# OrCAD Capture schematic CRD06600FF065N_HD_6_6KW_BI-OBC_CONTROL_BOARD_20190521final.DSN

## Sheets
1 PAGE5: size A3; title: 6.6kW HD Bi-directional OBC Control Board; rev: 3; note: P/N: CRD06600FF065N
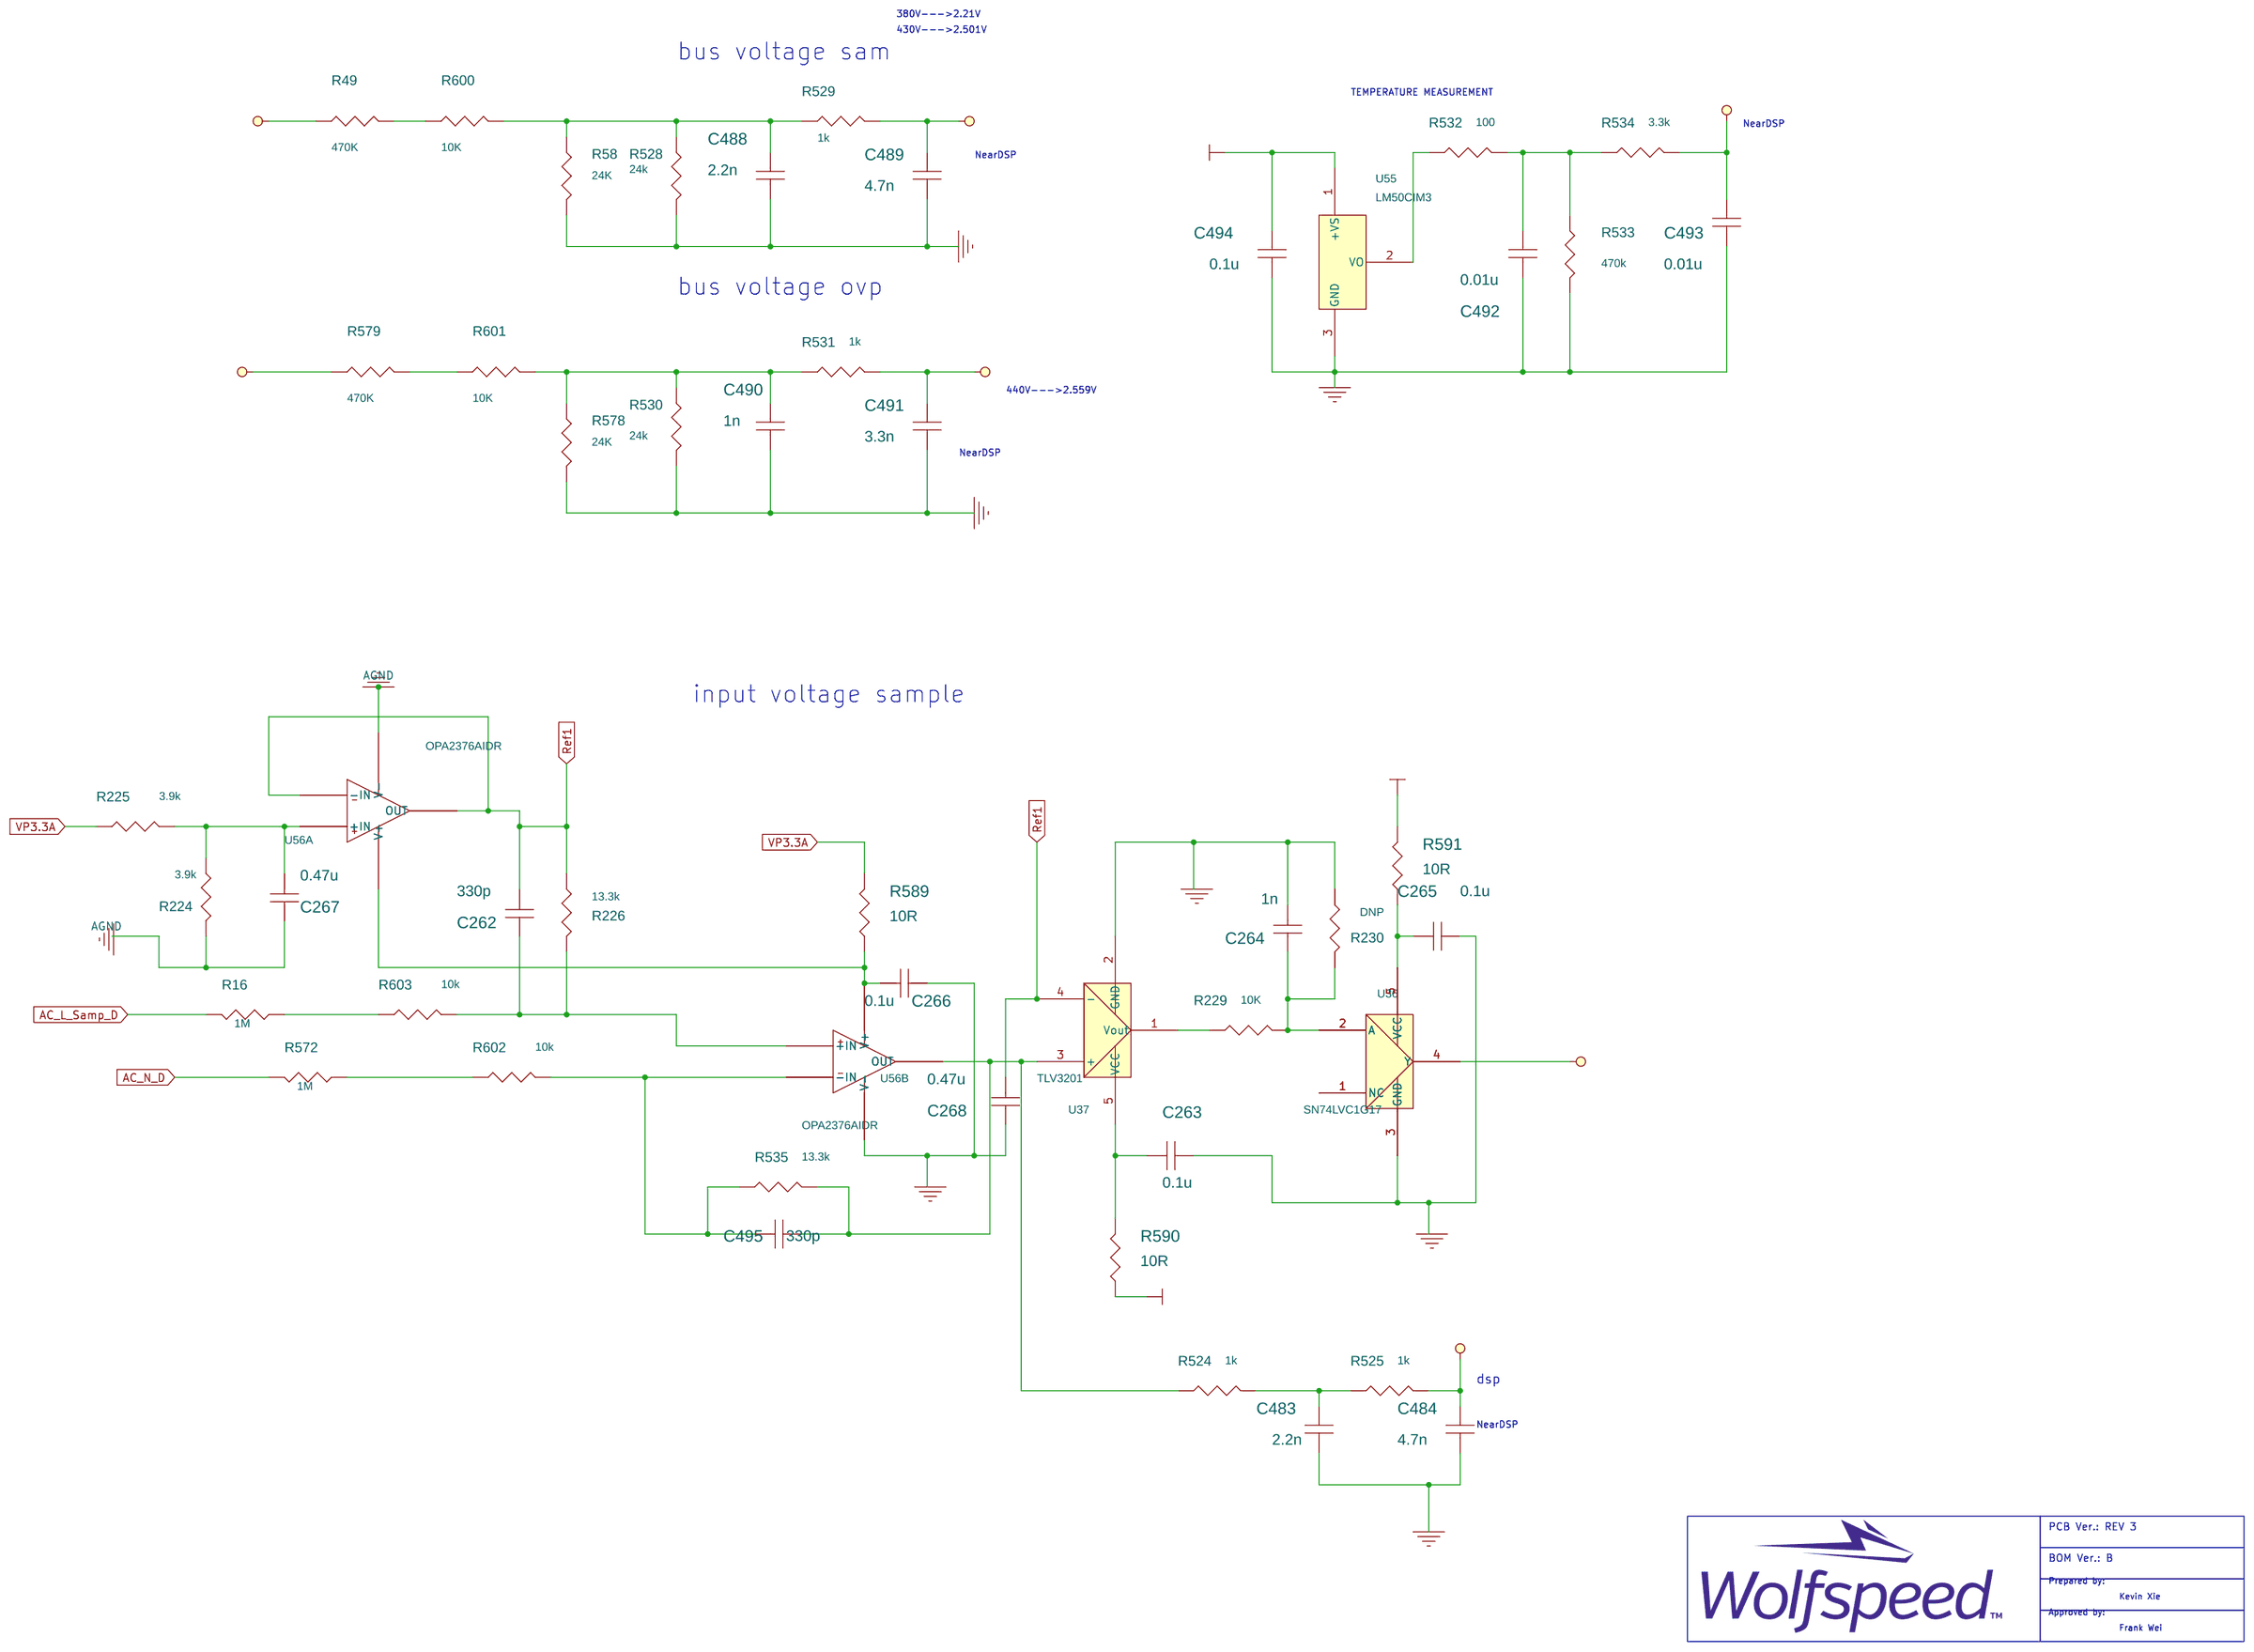
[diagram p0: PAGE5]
2 PAGE4: size A3
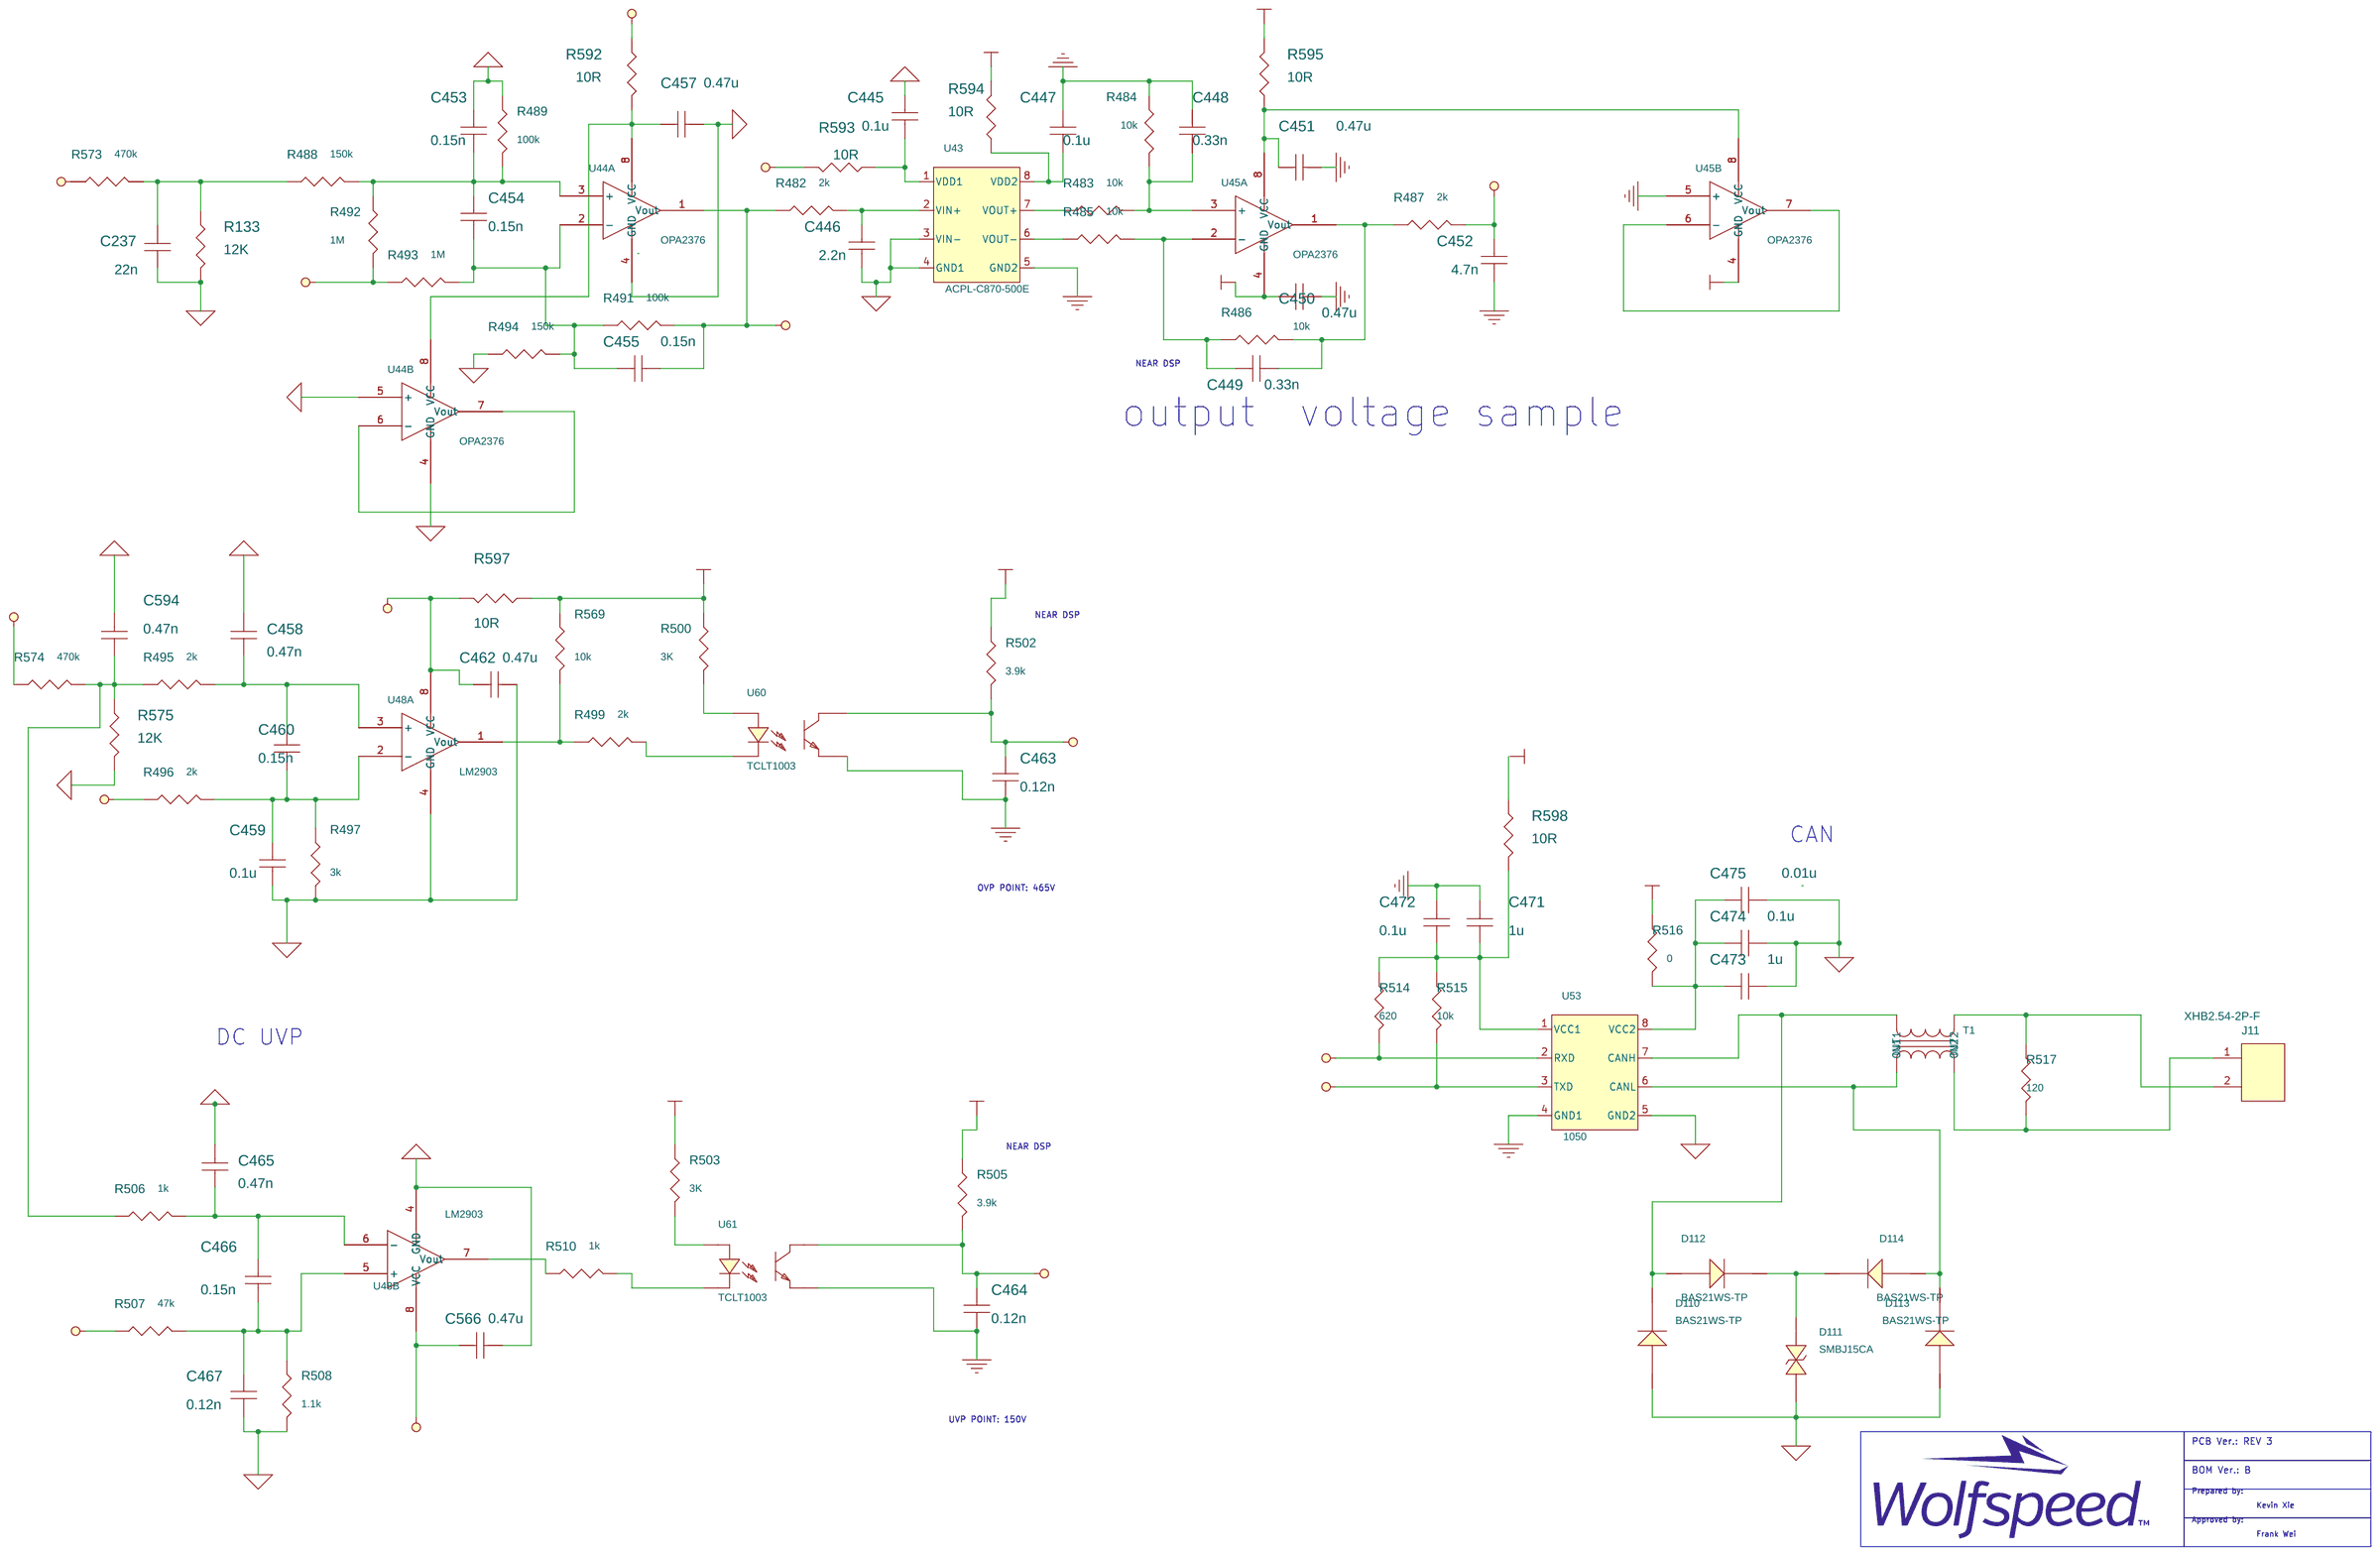
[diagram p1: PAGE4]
3 PAGE3: size A2
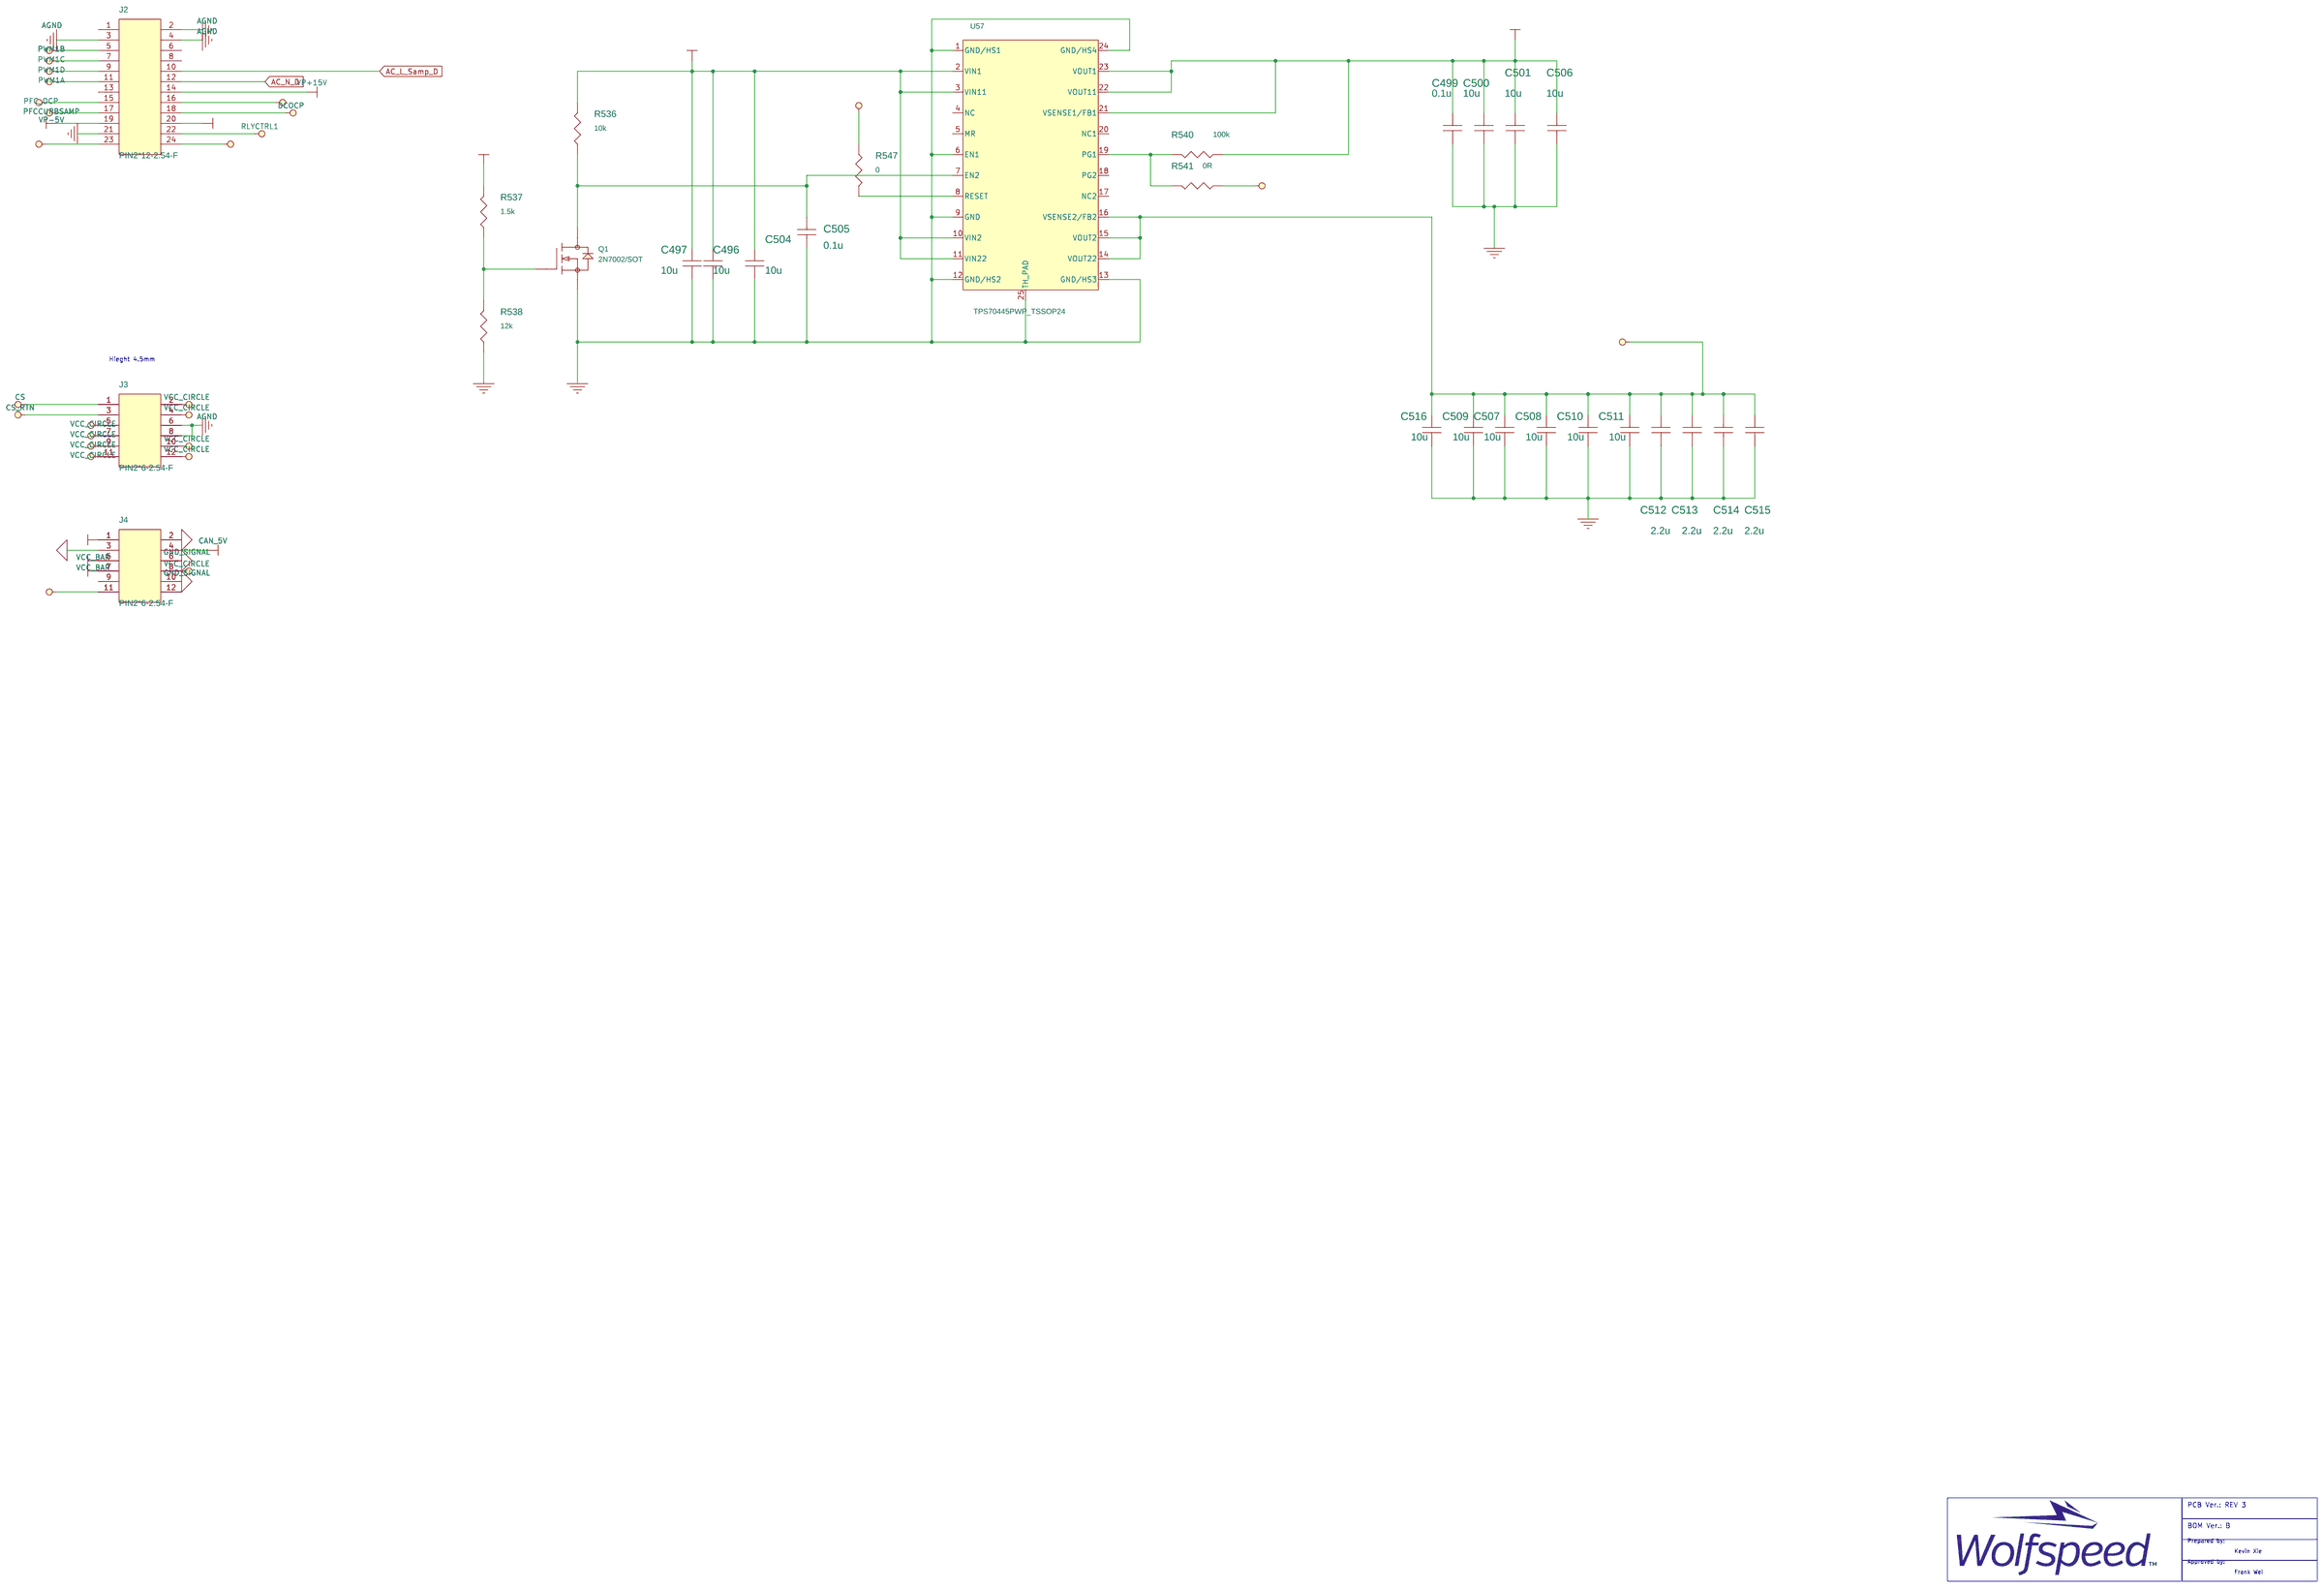
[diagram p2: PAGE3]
4 PAGE2: size A3
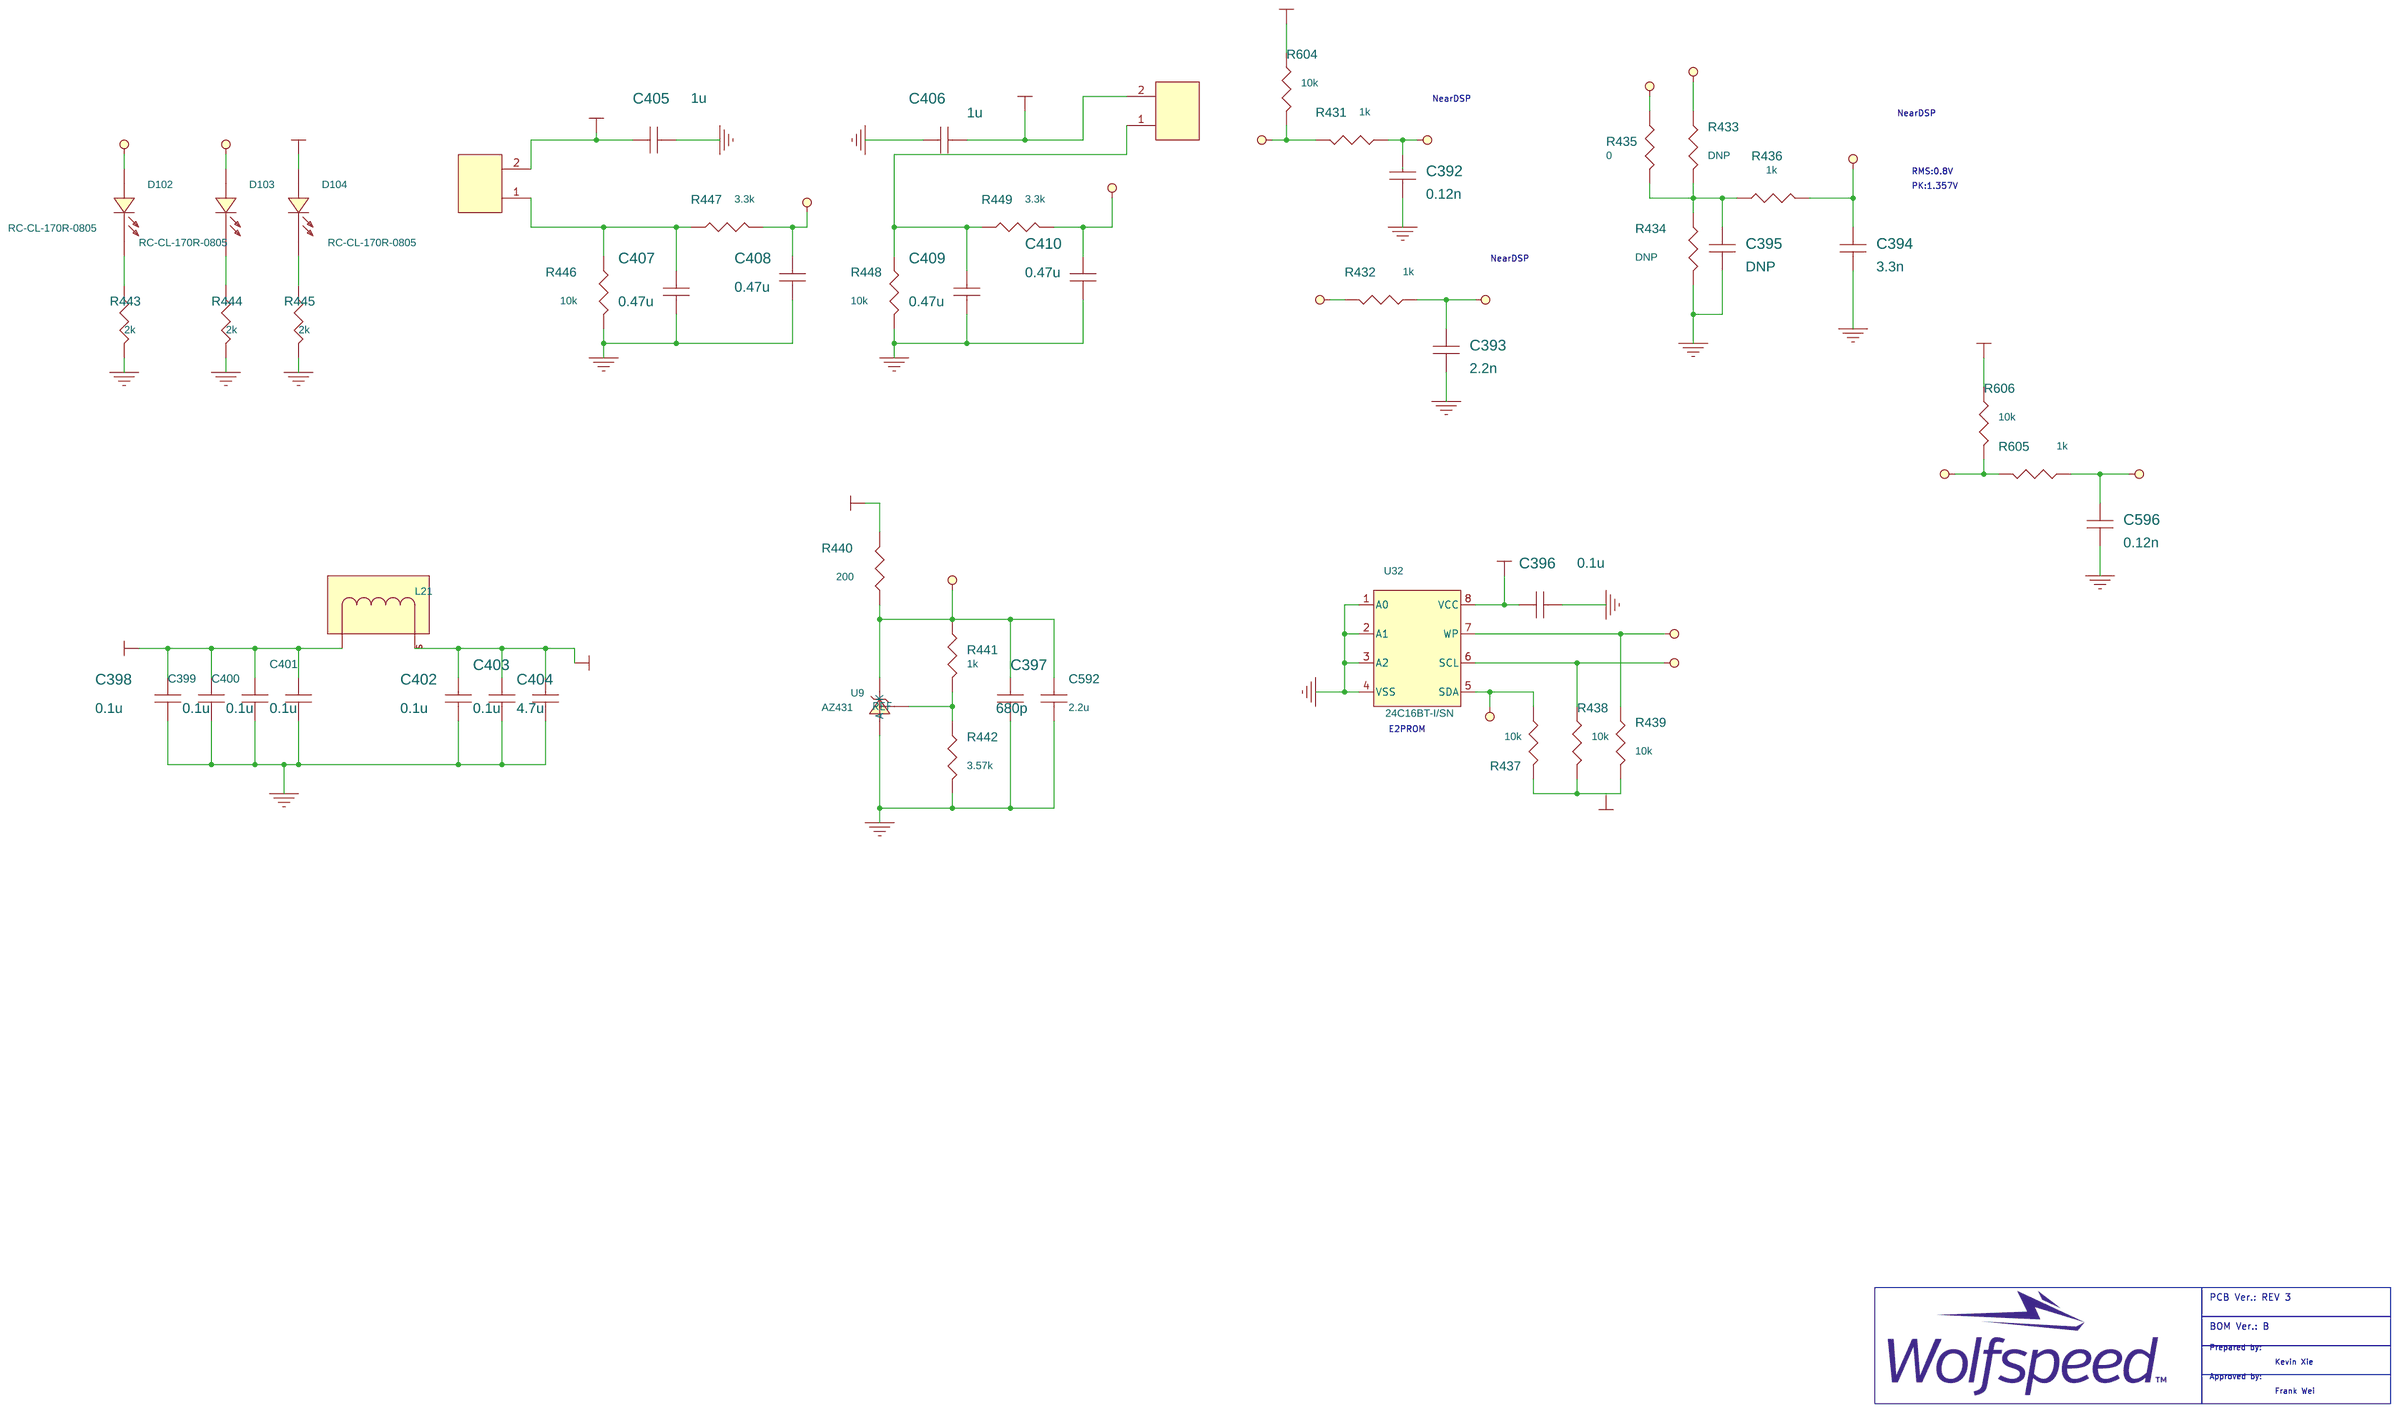
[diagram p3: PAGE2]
5 PAGE1: size C
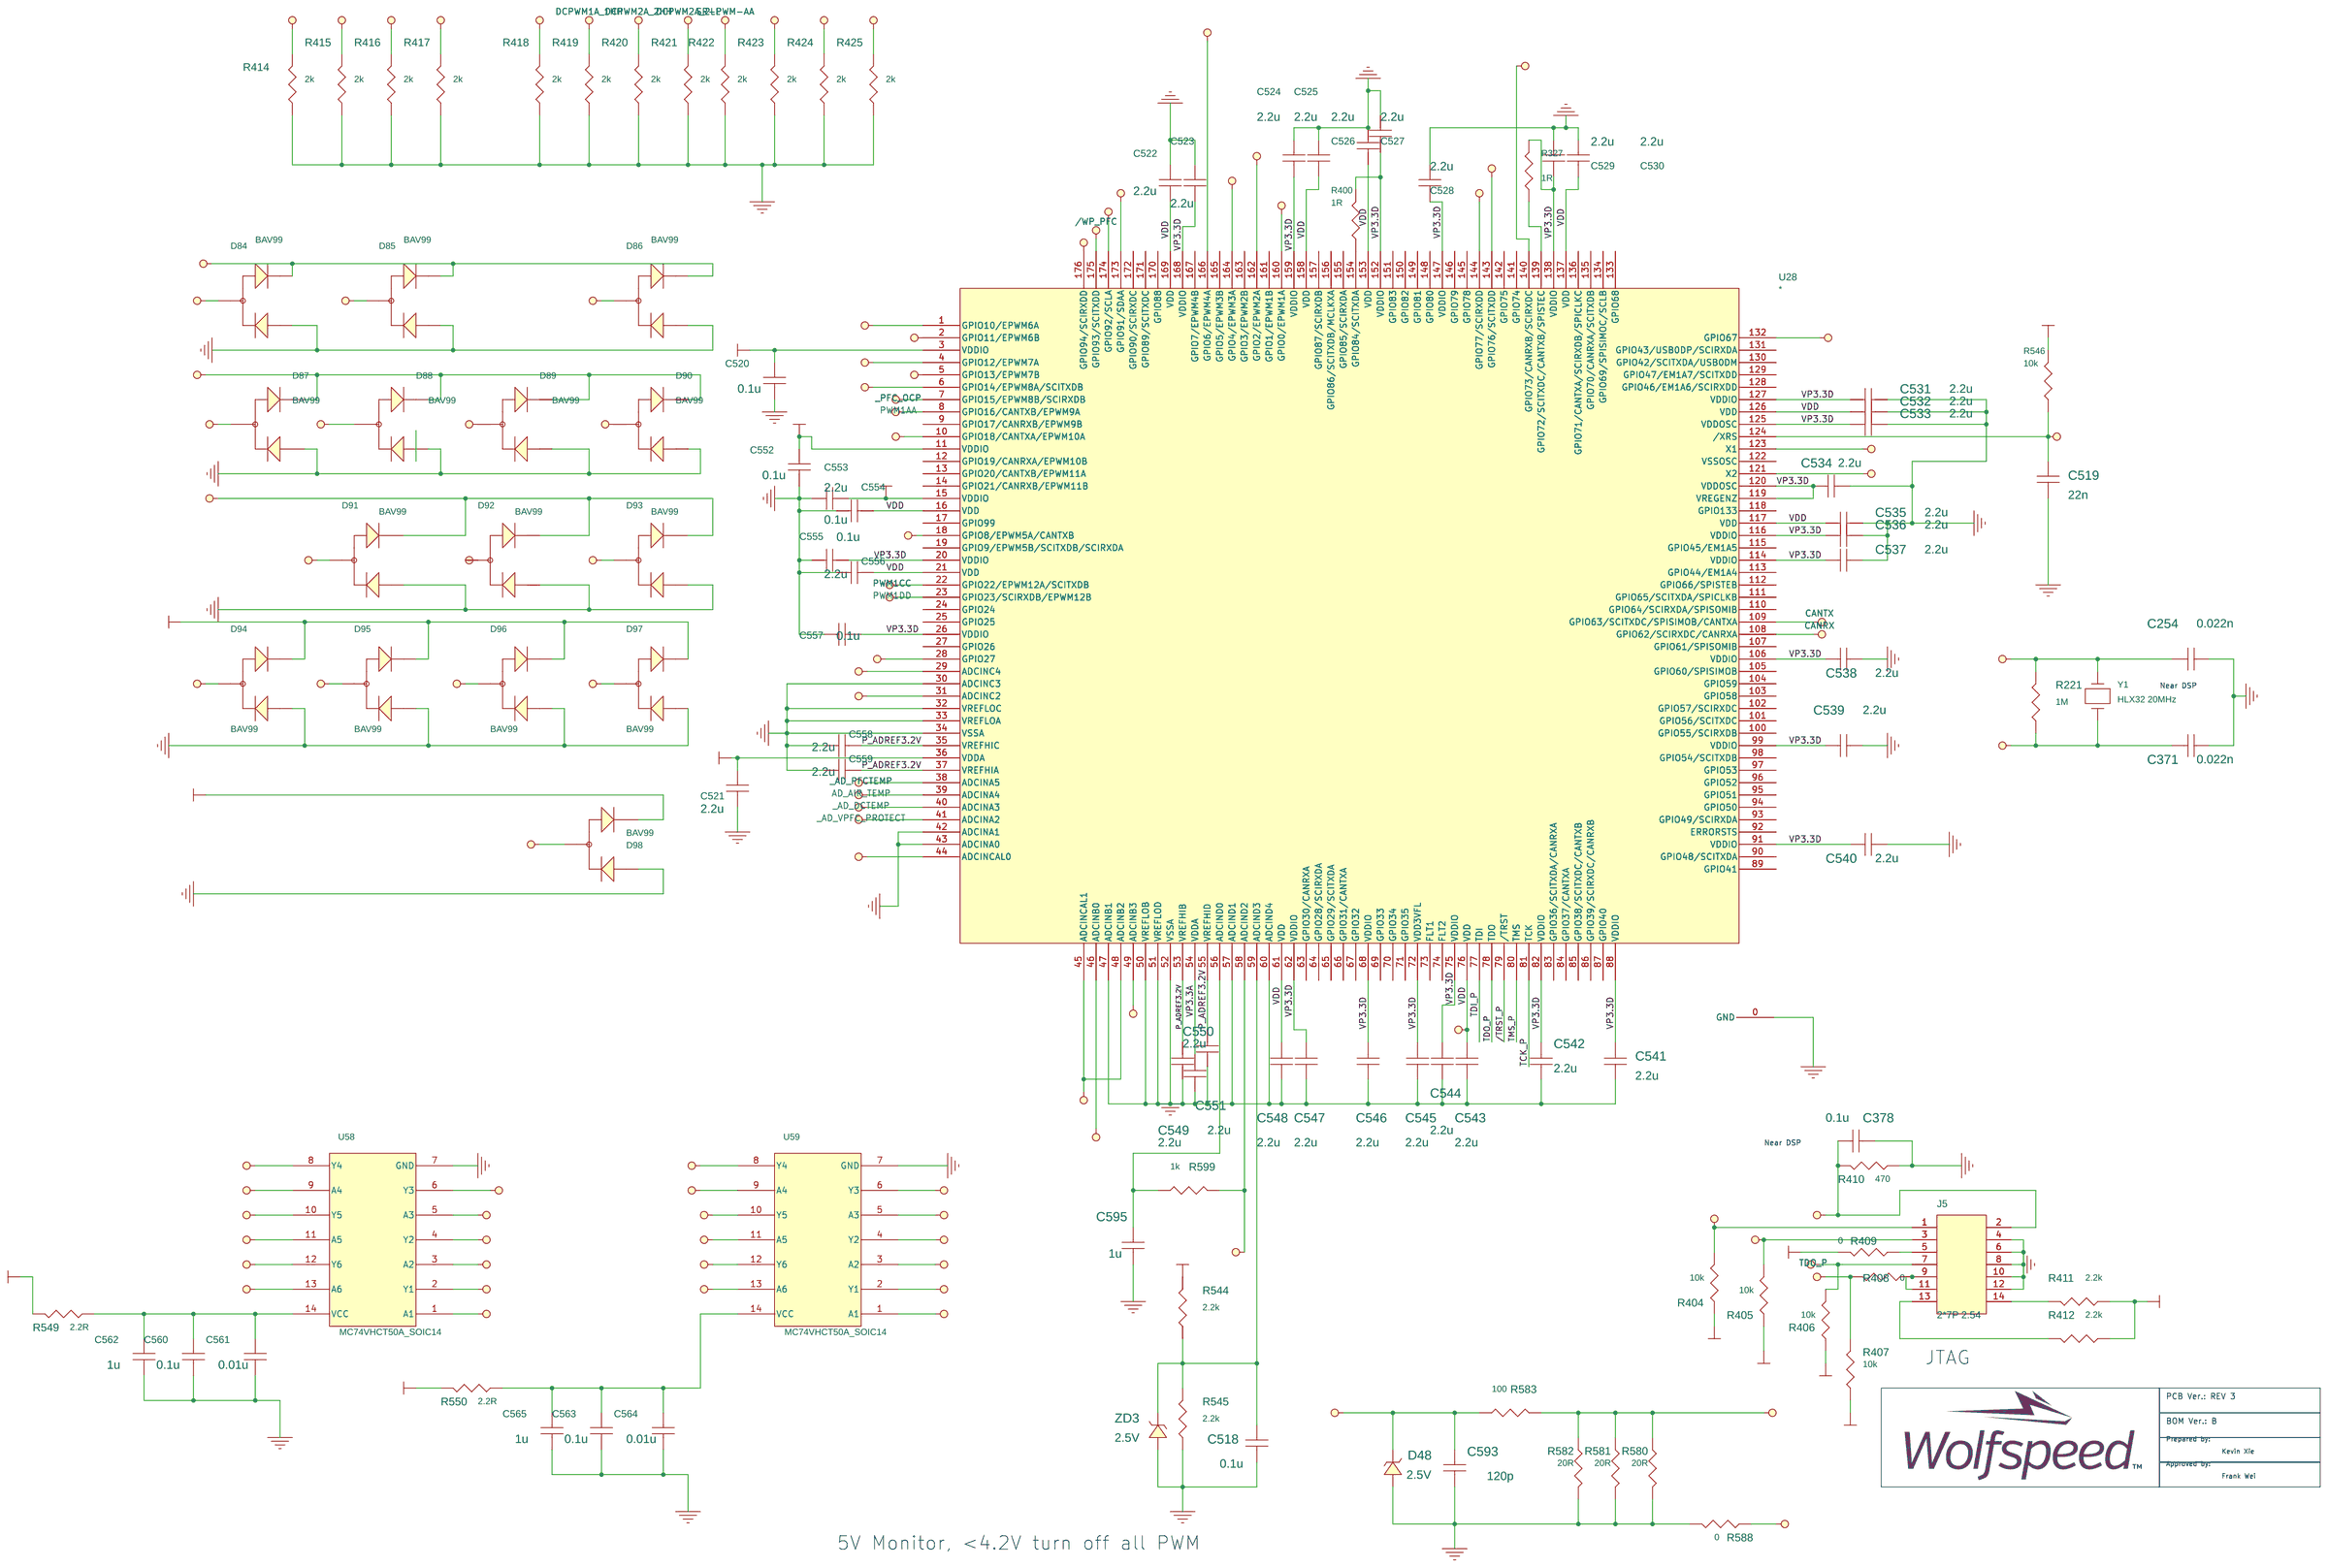
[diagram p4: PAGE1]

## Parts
sheet PAGE1
C254  0.022n  [C0603]
C371  0.022n  [C0603]
C378  0.1u  [C0603]
C518  0.1u  [C0603]
C519  22n  [C0603]
C520  0.1u  [C0603]
C521  2.2u  [C0603]
C522  2.2u  [C0603]
C523  2.2u  [C0603]
C524  2.2u  [C0603]
C525  2.2u  [C0603]
C526  2.2u  [C0603]
C527  2.2u  [C0603]
C528  2.2u  [C0603]
C529  2.2u  [C0603]
C530  2.2u  [C0603]
C531  2.2u  [C0603]
C532  2.2u  [C0603]
C533  2.2u  [C0603]
C534  2.2u  [C0603]
C535  2.2u  [C0603]
C536  2.2u  [C0603]
C537  2.2u  [C0603]
C538  2.2u  [C0603]
C539  2.2u  [C0603]
C540  2.2u  [C0603]
C541  2.2u  [C0603]
C542  2.2u  [C0603]
C543  2.2u  [C0603]
C544  2.2u  [C0603]
C545  2.2u  [C0603]
C546  2.2u  [C0603]
C547  2.2u  [C0603]
C548  2.2u  [C0603]
C549  2.2u  [C0603]
C550  2.2u  [C0603]
C551  2.2u  [C0603]
C552  0.1u  [C0603]
C553  0.1u  [C0603]
C554  2.2u  [C0603]
C555  0.1u  [C0603]
C556  2.2u  [C0603]
C557  0.1u  [C0603]
C558  2.2u  [C0603]
C559  2.2u  [C0603]
C560  0.1u  [C0603]
C561  0.01u  [C0603]
C562  1u  [C0603]
C563  0.1u  [C0603]
C564  0.01u  [C0603]
C565  1u  [C0603]
C593  120p  [C0603]
C595  1u  [C0603]
D48  2.5V  [SOD-123]
D84  BAV99  [SOT-23]
D85  BAV99  [SOT-23]
D86  BAV99  [SOT-23]
D87  BAV99  [SOT-23]
D88  BAV99  [SOT-23]
D89  BAV99  [SOT-23]
D90  BAV99  [SOT-23]
D91  BAV99  [SOT-23]
D92  BAV99  [SOT-23]
D93  BAV99  [SOT-23]
D94  BAV99  [SOT-23]
D95  BAV99  [SOT-23]
D96  BAV99  [SOT-23]
D97  BAV99  [SOT-23]
D98  BAV99  [SOT-23]
J5  2*7P 2.54  [con_2mm54_7x2]
R221  1M  [R0603]
R327  1R  [R0603]
R400  1R  [R0603]
R404  10k  [R0603]
R405  10k  [R0603]
R406  10k  [R0603]
R407  10k  [R0603]
R408  0  [R0603]
R409  0  [R0603]
R410  470  [R0603]
R411  2.2k  [R0603]
R412  2.2k  [R0603]
R414  2k  [R0603]
R415  2k  [R0603]
R416  2k  [R0603]
R417  2k  [R0603]
R418  2k  [R0603]
R419  2k  [R0603]
R420  2k  [R0603]
R421  2k  [R0603]
R422  2k  [R0603]
R423  2k  [R0603]
R424  2k  [R0603]
R425  2k  [R0603]
R544  2.2k  [R0603]
R545  2.2k  [R0603]
R546  10k  [R1206]
R549  2.2R  [R0603]
R550  2.2R  [R0603]
R580  20R  [R1206]
R581  20R  [R1206]
R582  20R  [R1206]
R583  100  [R0603]
R588  0  [R0603]
R599  1k  [R0603]
U28  TMS320F28377D  [LQFP176-050-2424]
U58  MC74VHCT50A_SOIC14  [SOIC14]
U59  MC74VHCT50A_SOIC14  [SOIC14]
Y1  HLX32 20MHz  [TSX-3225]
ZD3  2.5V  [SOD-323]
sheet PAGE2
C392  0.12n  [C0603]
C393  2.2n  [C0603]
C394  3.3n  [C0603]
C395  DNP  [C0603]
C396  0.1u  [C0603]
C397  680p  [C0603]
C398  0.1u  [C0603]
C399  0.1u  [C0603]
C400  0.1u  [C0603]
C401  0.1u  [C0603]
C402  0.1u  [C0603]
C403  0.1u  [C0603]
C404  4.7u  [c1206]
C405  1u  [C0603]
C406  1u  [C0603]
C407  0.47u  [C0603]
C408  0.47u  [C0603]
C409  0.47u  [C0603]
C410  0.47u  [C0603]
C592  2.2u  [C0805]
C596  0.12n  [C0603]
D102  RC-CL-170R-0805  [led0805]
D103  RC-CL-170R-0805  [led0805]
D104  RC-CL-170R-0805  [led0805]
J17  1*2P  [connect_2mm54_2x1]
J18  1*2P  [connect_2mm54_2x1]
L21  33uH 0.2A  [R0805]
R431  1k  [R0603]
R432  1k  [R0603]
R433  DNP  [R0603]
R434  DNP  [R0603]
R435  0  [R0603]
R436  1k  [R0603]
R437  10k  [R0603]
R438  10k  [R0603]
R439  10k  [R0603]
R440  200  [R0603]
R441  1k  [R0603]
R442  3.57k  [R0603]
R443  2k  [R0603]
R444  2k  [R0603]
R445  2k  [R0603]
R446  10k  [R0603]
R447  3.3k  [R0603]
R448  10k  [R0603]
R449  3.3k  [R0603]
R604  10k  [R0603]
R605  1k  [R0603]
R606  10k  [R0603]
U9  AZ431  [SOT23_1-32]
U32  24C16BT-I/SN  [SOIC-8]
sheet PAGE3
C496  10u  [C1206]
C497  10u  [C1206]
C499  0.1u  [C0603]
C500  10u  [c1206]
C501  10u  [c1206]
C504  10u  [C1206]
C505  0.1u  [C0603]
C506  10u  [c1206]
C507  10u  [C1206]
C508  10u  [C1206]
C509  10u  [C1206]
C510  10u  [C1206]
C511  10u  [C1206]
C512  2.2u  [C0805]
C513  2.2u  [C0805]
C514  2.2u  [C0805]
C515  2.2u  [C0805]
C516  10u  [C1206]
J2  PIN2*12-2.54-F  [con_2mm54_12x2]
J3  PIN2*6-2.54-F  [con_2mm54_6x2]
J4  PIN2*6-2.54-F  [con_2mm54_6x2]
Q1  2N7002/SOT  [SOT-23]
R536  10k  [R0603]
R537  1.5k  [R0603]
R538  12k  [R0603]
R540  100k  [R0603]
R541  0R  [R0603]
R547  0  [R0603]
U57  TPS70445PWP_TSSOP24  [TSSOP24]
sheet PAGE4
C237  22n  [C0603]
C445  0.1u  [C0603]
C446  2.2n  [C0603]
C447  0.1u  [C0603]
C448  0.33n  [C0603]
C449  0.33n  [C0603]
C450  0.47u  [C0603]
C451  0.47u  [C0603]
C452  4.7n  [C0603]
C453  0.15n  [C0603]
C454  0.15n  [C0603]
C455  0.15n  [C0603]
C457  0.47u  [C0603]
C458  0.47n  [C0603]
C459  0.1u  [C0603]
C460  0.15n  [C0603]
C462  0.47u  [C0603]
C463  0.12n  [C0603]
C464  0.12n  [C0603]
C465  0.47n  [C0603]
C466  0.15n  [C0603]
C467  0.12n  [C0603]
C471  1u  [C0603]
C472  0.1u  [C0603]
C473  1u  [C0603]
C474  0.1u  [C0603]
C475  0.01u  [C0603]
C566  0.47u  [C0603]
C594  0.47n  [C0603]
D110  BAS21WS-TP  [SOD-323]
D111  SMBJ15CA  [SMB]
D112  BAS21WS-TP  [SOD-323]
D113  BAS21WS-TP  [SOD-323]
D114  BAS21WS-TP  [SOD-323]
J11  XHB2.54-2P-F  [con_2mm54_2x1]
R133  12K  [R0603]
R482  2k  [R0603]
R483  10k  [R0603]
R484  10k  [R0603]
R485  10k  [R0603]
R486  10k  [R0603]
R487  2k  [R0603]
R488  150k  [R0603]
R489  100k  [R0603]
R491  100k  [R0603]
R492  1M  [R0603]
R493  1M  [R0603]
R494  150k  [R0603]
R495  2k  [R0603]
R496  2k  [R0603]
R497  3k  [R0603]
R499  2k  [R0603]
R500  3K  [R0603]
R502  3.9k  [R0603]
R503  3K  [R0603]
R505  3.9k  [R0603]
R506  1k  [R0603]
R507  47k  [R0603]
R508  1.1k  [R0603]
R510  1k  [R0603]
R514  620  [R0603]
R515  10k  [R0603]
R516  0  [R0603]
R517  120  [R0603]
R569  10k  [R0603]
R573  470k  [R1206]
R574  470k  [R1206]
R575  12K  [R0603]
R592  10R  [R0603]
R593  10R  [R0603]
R594  10R  [R0603]
R595  10R  [R0603]
R597  10R  [R0603]
R598  10R  [R0603]
T1  TRNSFMR TV105  [ZJYS81]
U43  ACPL-C870-500E  [SSO-8]
U44  OPA2376  [SOIC-8]  (sections A,B)
U45  OPA2376  [SOIC-8]  (sections A,B)
U48  LM2903  [SOIC-8]  (sections A,B)
U53  1050  [SO-G8]
U60  TCLT1003  [tclt1003]
U61  TCLT1003  [tclt1003]
sheet PAGE5
C262  330p  [C0603]
C263  0.1u  [C0603]
C264  1n  [C0603]
C265  0.1u  [C0603]
C266  0.1u  [C0603]
C267  0.47u  [C0603]
C268  0.47u  [C0603]
C483  2.2n  [C0603]
C484  4.7n  [C0603]
C488  2.2n  [C0603]
C489  4.7n  [C0603]
C490  1n  [C0603]
C491  3.3n  [C0603]
C492  0.01u  [C0603]
C493  0.01u  [C0603]
C494  0.1u  [C0603]
C495  330p  [C0603]
R16  1M  [R1206]
R49  470K  [R1206]
R58  24K  [R0603]
R224  3.9k  [R0603]
R225  3.9k  [R0603]
R226  13.3k  [R0603]
R229  10K  [R0603]
R230  DNP  [R0603]
R524  1k  [R0603]
R525  1k  [R0603]
R528  24k  [R0603]
R529  1k  [R0603]
R530  24k  [R0603]
R531  1k  [R0603]
R532  100  [R0603]
R533  470k  [R0603]
R534  3.3k  [R0603]
R535  13.3k  [R0603]
R572  1M  [R1206]
R578  24K  [R0603]
R579  470K  [R1206]
R589  10R  [R0603]
R590  10R  [R0603]
R591  10R  [R0603]
R600  10K  [R0603]
R601  10K  [R0603]
R602  10k  [R0603]
R603  10k  [R0603]
U36  SN74LVC1G17  [DCK]
U37  TLV3201  [SOT23-5]
U55  LM50CIM3  [SOT-23]
U56  OPA2376AIDR  [WCSP-8]  (sections A,B)

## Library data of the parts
C237 C254 C262-C268 C371 C378 C392-C410 C445-C455 C457-C460 C462-C467 C471-C475 C483 C484 C488-C497 C499-C501 C504-C516 C518-C566 C592-C596 = CAP_NP
D48 ZD3 = DIODE_ZENER_0
D84-D98 = BAS70-04_SOT
J5 = 2*7P: Part Label: 2*7P 2.54 直针; Part number: 621000812; Part_Name: 连接器; Unit: PCS
R16 R49 R58 R221 R224-R226 R229 R230 R404-R412 R414-R425 R431-R449 R482-R489 R491-R497 R499 R500 R502 R503 R505-R508 R510 R514-R517 R524 R525 R528-R538 R540 R541 R544 R545 R547 R549 R550 R569 R572-R574 R578-R583 R588 R599-R606 = RESISTOR
R133 R327 R400 R546 R575 R589-R595 R597 R598 = R
U28 = TMS320F28377D: Comment_1: *; Manufacturers Part: TI; Part number: 606800054; Type: IC
U58 U59 = MC74VHCT50A_SOIC14
Y1 = CRYSTAL2-4_SM_0
D102-D104 = CCL-CRS10_SM
J17 J18 = 1*2P
L21 = 126LNS_4
U9 = LEU094_ZTL431AFTA_SOT23_0: LLF Part Number: LEU072
U32 = 24C16BT-I_SN
J2 = 2*12P: Part Label: PIN2*12-2.54-F 直针; Part number: 621000132; Part_Name: 双排直针; Unit: PCS
J3 J4 = 2*6P: Part Label: PIN2*6-2.54-F 直针; Part number: 621000134; Part_Name: 双排直针; Unit: PCS
Q1 = 2N7002_SOT
U57 = TPS70445PWP_TSSOP24
D110 = BAS21_SOT_1
D111 = DIODE_BI-DIR_TRIG
D112 = BAS21_SOT_2
D113 = BAS21_SOT_4
D114 = BAS21_SOT_3
J11 = 1*2P: Manufacturers Part: 浙江硕正电气; Part Label: connect_2mm54_2x1; Part number: 621000044; Part_Name: 插座; Unit: PCS
T1 = TRNSFMR_TV105_0
U43 = 24C16BT-I_SN_0
U44 U45 U48 = LM2904
U53 = 24C16BT-I_SN_2
U60 U61 = LEU169_TCLT1003_SOP-4L
U36 = TLV3201_0
U37 = TLV3201
U55 = MC78L05F-TP_0
U56 = LM293A: Package: 1

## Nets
AGND: C254.1 C263.1 C264.2 C265.1 C266.1 C267.1 C268.1 C371.1 C378.2 C392.2 C393.2 C394.2 C395.2 C396.2 C397.2 C398.2 C399.2 C400.2 C401.2 C402.2 C403.2 C404.2 C405.2 C406.1 C407.2 C408.2 C409.2 C410.2 C447.1 C448.1 C450.2 C451.2 C452.2 C463.2 C464.2 C471.2 C472.2 C483.2 C484.2 C488.2 C489.2 C490.2 C491.2 C492.2 C493.2 C494.2 C496.2 C497.2 C499.2 C500.2 C501.2 C504.2 C505.2 C506.2 C507.2 C508.2 C509.2 C510.2 C511.2 C512.2 C513.2 C514.2 C515.2 C516.2 C518.2 C519.2 C520.2 C521.2 C522.1 C523.1 C524.1 C525.1 C526.1 C527.1 C528.1 C529.1 C530.1 C531.2 C532.2 C533.2 C534.2 C535.2 C536.2 C537.2 C538.2 C539.2 C540.2 C541.1 C542.1 C543.1 C544.1 C545.1 C546.1 C547.1 C548.1 C549.1 C550.1 C551.1 C552.2 C553.1 C554.1 C555.1 C556.1 C557.1 C558.1 C559.1 C560.2 C561.2 C562.2 C563.2 C564.2 C565.2 C592.2 C593.2 C595.2 C596.2 D48.1(ANODE) D84.1 D85.1 D86.1 D87.1 D88.1 D89.1 D90.1 D91.1 D92.1 D93.1 D94.1 D95.1 D96.1 D97.1 D98.1 J2.2 J2.3 J2.4 J2.21 J3.6 J3.8 J5.4 J5.6 J5.8 J5.10 J5.12 Q1.2(SOURCE) R58.1 R224.2 R230.1 R410.1 R414.1 R415.1 R416.1 R417.1 R418.1 R419.1 R420.1 R421.1 R422.1 R423.1 R424.1 R425.1 R434.2 R442.2 R443.2 R444.2 R445.2 R446.2 R448.2 R484.1 R528.2 R530.2 R533.2 R538.1 R545.1 R578.1 R580.1 R581.1 R582.1 R588.2 U9.3(A) U28.0(GND) U28.30(ADCINC3) U28.32(VREFLOC) U28.33(VREFLOA) U28.34(VSSA) U28.42(ADCINA1) U28.43(ADCINA0) U28.47(ADCINB1) U28.50(VREFLOB) U28.51(VREFLOD) U28.52(VSSA) U28.57(ADCIND1) U28.60(ADCIND4) U32.1(A0) U32.2(A1) U32.3(A2) U32.4(VSS) U36.3(GND) U37.2(GND) U43.5(GND2) U45.5(+) U53.4(GND1) U55.3(GND) U56.4(V-) U57.1(GND/HS1) U57.6(EN1) U57.9(GND) U57.12(GND/HS2) U57.13(GND/HS3) U57.24(GND/HS4) U57.25(TH_PAD) U58.7(GND) U59.7(GND) U60.3 U61.3 ZD3.1(ANODE)
DGND: C237.1 C445.1 C446.2 C453.1 C457.2 C458.2 C459.2 C462.2 C465.2 C467.2 C566.2 C594.2 J4.3 J4.6 J4.10 R133.2 R489.1 R494.1 R497.2 R508.2 R575.2 U43.3(VIN-) U43.4(GND1) U44.4(GND) U44.5(+) U48.4(GND)
VDD: C507.1 C508.1 C509.1 C510.1 C511.1 C512.1 C513.1 C514.1 C515.1 C516.1 C522.2 C525.2 C526.2 C530.2 C532.1 C535.1 C543.2 C548.2 C554.2 C556.2 U28.16(VDD) U28.21(VDD) U28.61(VDD) U28.76(VDD) U28.117(VDD) U28.126(VDD) U28.137(VDD) U28.153(VDD) U28.158(VDD) U28.169(VDD) U57.14(VOUT22) U57.15(VOUT2) U57.16(VSENSE2/FB2)
/TRST_P: C378.1 J5.2 R410.2 U28.79(/TRST)
/WP_PFC: R439.1 U28.175(GPIO93/SCITXDD) U32.7(WP)
_AD_DC_CUR: C393.1 D90.3 R432.1 U28.45(ADCINCAL1) U28.48(ADCINB2)
_AD_DCTEMP: C408.1 D92.3 R447.2 U28.40(ADCINA3)
_AD_PFCTEMP: C410.1 D84.3 R449.2 U28.38(ADCINA5)
_AD_VAC: C484.1 D88.3 R525.2 U28.29(ADCINC4)
_AD_Vpfc_Ctrl: C489.1 D93.3 R529.2 U28.31(ADCINC2)
_AD_Vpfc_Protect: C491.1 D91.3 R531.2 U28.41(ADCINA2) U28.49(ADCINB3)
_DCOCP: C392.1 D95.3 R431.1 U28.2(GPIO11/EPWM6B)
_PFC_OCP: C596.1 R605.1 U28.7(GPIO15/EPWM8B/SCIRXDB)
_PFCCURBSAMP: C394.1 D87.3 R436.2 U28.44(ADCINCAL0)
AC_L_Samp_D: J2.10 R16.1
AC_N_D: J2.12 R572.1
AD_AIR_TEMP: C493.1 D85.3 R534.2 U28.39(ADCINA4)
AD_DC_CUR: J2.16 R432.2
AD_DCVOLT1: C452.1 D89.3 R487.2 U28.46(ADCINB0)
CAN5V_GND: C473.2 C474.2 C475.2 D110.1(ANODE) D111.1 D113.1(ANODE) J4.2 U53.5(GND2)
CAN_5V: J4.4 R516.1
CANRX: R514.2 U28.108(GPIO62/SCIRXDC/CANRXA) U53.2(RXD)
CANTX: R515.2 U28.109(GPIO63/SCITXDC/SPISIMOB/CANTXA) U28.140(GPIO73/CANRXB/SCIRXDC) U53.3(TXD)
CS: J3.1 R580.2 R581.2 R582.2 R583.1
CS_ADC: C593.1 D48.2(CATHODE) R583.2 R599.1 U28.58(ADCIND2)
CS_RTN: J3.3 R588.1
DCOCP: J2.18 R431.2 R604.2
DCOVP: C463.1 D98.3 R502.2 U28.176(GPIO94/SCIRXDD) U60.4
DCPWM1A_1H: J3.4 U58.6(Y3)
DCPWM1A_1HH: R419.2 U28.160(GPIO0/EPWM1A) U58.5(A3)
DCPWM1A_1L: J3.2 U58.4(Y2)
DCPWM1A_1LL: R418.2 U28.162(GPIO2/EPWM2A) U58.3(A2)
DCPWM2A_2H: J3.7 U58.12(Y6)
DCPWM2A_2HH: R420.2 U28.164(GPIO4/EPWM3A) U58.13(A6)
DCPWM2A_2L: J3.5 U58.2(Y1)
DCPWM2A_2LL: R421.2 U28.166(GPIO6/EPWM4A) U58.1(A1)
DCSHORT: C464.1 D94.3 R505.2 U28.5(GPIO13/EPWM7B) U61.4
DCVOLT1: C455.2 R482.1 R491.2 U44.1(Vout)
P_ADREF3.2V: C397.1 C549.2 C551.2 C558.2 C559.2 C592.1 D84.2 D85.2 D86.2 D87.2 D88.2 D89.2 D90.2 D91.2 D92.2 D93.2 R433.1 R440.1 R441.1 U9.2(K) U28.35(VREFHIC) U28.37(VREFHIA) U28.53(VREFHIB) U28.55(VREFHID)
P_SCL: R438.1 U28.174(GPIO92/SCLA) U32.6(SCL)
P_SDA: R437.1 U28.173(GPIO91/SDAA) U32.5(SDA)
P_WD_GREEN: D102.2(ANODE) U28.143(GPIO76/SCITXDD)
P_WD_RED: D103.2(ANODE) U28.144(GPIO77/SCIRXDD)
PFC-FB: J2.23 R49.2
PFC-VO: J2.24 R579.2
PFC_OCP: D96.3 J2.15 R605.2 R606.2
PFCCURBSAMP: J2.17 R435.1
PWM1A: J2.11 U58.8(Y4)
PWM1AA: R414.2 U28.8(GPIO16/CANTXB/EPWM9A) U58.9(A4)
PWM1B: J2.5 U58.10(Y5)
PWM1BB: R415.2 U28.10(GPIO18/CANTXA/EPWM10A) U58.11(A5)
PWM1C: J2.7 U59.8(Y4)
PWM1CC: R416.2 U28.22(GPIO22/EPWM12A/SCITXDB) U59.9(A4)
PWM1D: J2.9 U59.10(Y5)
PWM1DD: R417.2 U28.23(GPIO23/SCIRXDB/EPWM12B) U59.11(A5)
Ref1: C262.2 C268.2 R226.1 U37.4(-) U56.1(OUT) U56.2(-IN)
RLYCTRL1: D97.3 J2.22 U28.132(GPIO67)
SR-PWM-A: J3.9 U59.12(Y6)
SR-PWM-AA: R422.2 U28.18(GPIO8/EPWM5A/CANTXB) U59.13(A6)
SR-PWM-B: J3.10 U59.2(Y1)
SR-PWM-BB: R423.2 U28.1(GPIO10/EPWM6A) U59.1(A1)
SR-PWM-C: J3.11 U59.4(Y2)
SR-PWM-CC: R424.2 U28.4(GPIO12/EPWM7A) U59.3(A2)
SR-PWM-D: J3.12 U59.6(Y3)
SR-PWM-DD: R425.2 U28.6(GPIO14/EPWM8A/SCITXDB) U59.5(A3)
TCK_P: R407.2 R408.2 U28.81(TCK)
TDI_P: J5.3 R405.2 U28.77(TDI)
TDO_P: J5.7 R406.2 U28.78(TDO)
TMS_P: J5.1 R404.2 U28.80(TMS)
VAC_Polarity+: D86.3 U28.28(GPIO27) U36.4(Y)
VO1+: J4.11 R574.1
VO2+: J4.8 R573.1
VP3.3A: C402.1 C403.1 C404.1 C521.1 C550.2 L21.1 R225.1 R589.2 R590.1 U28.36(VDDA) U28.54(VDDA)
VP3.3D: C396.1 C398.1 C399.1 C400.1 C401.1 C405.1 C406.2 C499.1 C500.1 C501.1 C506.1 C520.1 C523.2 C524.2 C527.2 C528.2 C529.2 C531.1 C533.1 C534.1 C536.1 C537.1 C538.1 C539.1 C540.1 C541.2 C542.2 C544.2 C545.2 C546.2 C547.2 C552.1 C553.2 C555.2 C557.2 D94.2 D95.2 D96.2 D97.2 D98.2 D104.2(ANODE) J17.2 J18.2 L21.2 R327.2 R400.2 R404.1 R405.1 R406.1 R407.1 R409.2 R411.1 R412.1 R437.2 R438.2 R439.2 R502.1 R505.1 R537.2 R540.1 R546.2 R591.2 R598.1 R604.1 R606.1 U28.3(VDDIO) U28.11(VDDIO) U28.15(VDDIO) U28.20(VDDIO) U28.26(VDDIO) U28.62(VDDIO) U28.68(VDDIO) U28.72(VDD3VFL) U28.75(VDDIO) U28.82(VDDIO) U28.88(VDDIO) U28.91(VDDIO) U28.99(VDDIO) U28.106(VDDIO) U28.114(VDDIO) U28.116(VDDIO) U28.119(VREGENZ) U28.120(VDDOSC) U28.125(VDDOSC) U28.127(VDDIO) U28.138(VDDIO) U28.147(VDDIO) U28.152(VDDIO) U28.159(VDDIO) U28.168(VDDIO) U32.8(VCC) U57.21(VSENSE1/FB1) U57.22(VOUT11) U57.23(VOUT1)
VP+5V: C494.1 C496.1 C497.1 C504.1 J2.20 R440.2 R536.2 R544.2 R549.2 R550.2 R594.2 R595.2 U55.1(+VS) U57.2(VIN1) U57.3(VIN11) U57.10(VIN2) U57.11(VIN22)
VP+15V: J2.14
VP-5V: C450.1 J2.19 U45.4(GND)
VS+5V: J4.7 R492.2 R493.1 R496.1 R507.1 R592.2 R593.2
VS+15V: J4.1 R500.1 R503.1 R569.1 R597.1
VS+15V_U48: C462.1 C566.1 R597.2 U48.8(VCC)
VS-5V: J4.5
X1: C371.2 R221.1 U28.123(X1) Y1.1(2)
X2: C254.2 R221.2 U28.121(X2) Y1.2(4)
XRS: C519.1 R541.1 R546.1 R547.1 U28.124(/XRS)
N16777869: J5.9 J5.11 R408.1
N16779815: R327.1 U28.139(GPIO72/SCITXDC/CANTXB/SPISTEC)
N16809513: J5.5 R409.1
N16810933: J5.13 R412.2
N16810951: J5.14 R411.2
N16824215: C395.1 R433.2 R434.1 R435.2 R436.1
N16830570: R441.2 R442.1 U9.1(REF)
N16833081: D102.1(CATHODE) R443.1
N16833084: D103.1(CATHODE) R444.1
N16833087: D104.1(CATHODE) R445.1
N16835391: C407.1 J17.1 R446.1 R447.1
N16836592: C409.1 J18.1 R448.1 R449.1
N16848574: C446.1 R482.2 U43.2(VIN+)
N16848598: C445.2 R593.1 U43.1(VDD1)
N16848614: C447.2 R594.1 U43.8(VDD2)
N16848642: R483.1 U43.7(VOUT+)
N16848644: C448.2 R483.2 R484.2 U45.3(+)
N16848814: R485.1 U43.6(VOUT-)
N16848816: C449.1 R485.2 R486.1 U45.2(-)
N16848832: C449.2 R486.2 R487.1 U45.1(Vout)
N16848970: U44.6(-) U44.7(Vout)
N16848978: C453.2 C454.1 R488.2 R489.2 R492.1 U44.3(+)
N16848994: C454.2 C455.1 R491.1 R493.2 R494.2 U44.2(-)
N16849016: C457.1 R592.1 U44.8(VCC)
N16851028: U45.6(-) U45.7(Vout)
N16851046: C451.1 R595.1 U45.8(VCC)
N16853569: C458.1 C460.1 R495.2 U48.3(+)
N16853931: C459.1 C460.2 R496.2 R497.1 U48.2(-)
N16853972: R499.1 R569.2 U48.1(Vout)
N16854569: R500.2 U60.1
N16855013: C466.2 C467.1 R507.2 R508.1 U48.5(+)
N16855828: C465.1 C466.1 R506.2 U48.6(-)
N16855912: R510.2 U61.2
N16855916: R503.2 U61.1
N16860426: C471.1 C472.1 R514.1 R515.1 R598.2 U53.1(VCC1)
N16860580: C473.1 C474.1 C475.1 R516.2 U53.8(VCC2)
N16860640: D110.2(CATHODE) D112.1(ANODE) T1.2(OUT1) U53.7(CANH)
N16861242: J11.2 R517.1 T1.3(OUT2)
N16861249: D113.2(CATHODE) D114.1(ANODE) T1.1(IN1) U53.6(CANL)
N16861268: J11.1 R517.2 T1.4(IN2)
N16861373: D111.2 D112.2(CATHODE) D114.2(CATHODE)
N16866679: C488.1 R58.2 R528.1 R529.1 R600.1
N16866735: C490.1 R530.1 R531.1 R578.2 R601.1
N16867200: C492.1 R532.2 R533.1 R534.1
N16867335: R532.1 U55.2(VO)
N16868074: C264.1 R229.2 R230.2 U36.2(A)
N16868076: R229.1 U37.1(Vout)
N16868126: C265.2 R591.1 U36.5(VCC)
N16868143: C266.2 R589.1 U56.8(V+)
N16868206: C495.2 R535.1 R602.2 U56.6(-IN)
N16868218: C495.1 R524.1 R535.2 U37.3(+) U56.7(OUT)
N16868269: C262.1 R226.2 R603.2 U56.5(+IN)
N16868287: C267.2 R224.1 R225.2 U56.3(+IN)
N16900365: Q1.1(GATE) R537.1 R538.2
N16900541: C505.1 Q1.3(DRAIN) R536.1 U57.7(EN2)
N16908509: R540.2 R541.2 U57.19(PG1)
N16911091: C263.2 R590.2 U37.5(VCC)
N16917336: C483.1 R524.2 R525.1
N16935004: R547.2 U57.8(RESET)
N16936023: C518.1 R544.1 R545.2 U28.59(ADCIND3) ZD3.2(CATHODE)
N17022031: C560.1 C561.1 C562.1 R549.1 U58.14(VCC)
N17025421: C563.1 C564.1 C565.1 R550.1 U59.14(VCC)
N17045637: R499.2 U60.2
N17046827: R510.1 U48.7(Vout)
N17085418: R400.1 U28.154(GPIO84/SCITXDA)
N17096901: C237.2 R133.1 R488.1 R573.2
N17102058: C594.1 R495.1 R506.1 R574.2 R575.1
N17145225: C595.1 R599.2 U28.56(ADCIND0)
N17156215: R579.1 R601.2
N17156241: R49.1 R600.2
N17158559: R16.2 R603.1
N17158583: R572.2 R602.1

Not connected (* = marked no-connect by the designer): J2 1 6 8 13; J4 9 12; U28 9(GPIO17/CANRXB/EPWM9B) 12(GPIO19/CANRXA/EPWM10B) 13(GPIO20/CANTXB/EPWM11A) 14(GPIO21/CANRXB/EPWM11B) 17(GPIO99) 19(GPIO9/EPWM5B/SCITXDB/SCIRXDA) 24(GPIO24) 25(GPIO25) 27(GPIO26) 63(GPIO30/CANRXA) 64(GPIO28/SCIRXDA) 65(GPIO29/SCITXDA) 66(GPIO31/CANTXA) 67(GPIO32) 69(GPIO33) 70(GPIO34) 71(GPIO35) 73(FLT1) 74(FLT2) 83(GPIO36/SCITXDA/CANRXA) 84(GPIO37/CANTXA) 85(GPIO38/SCITXDC/CANTXB) 86(GPIO39/SCIRXDC/CANRXB) 87(GPIO40) 89(GPIO41) 90(GPIO48/SCITXDA) 92(ERRORSTS) 93(GPIO49/SCIRXDA) 94(GPIO50) 95(GPIO51) 96(GPIO52) 97(GPIO53) 98(GPIO54/SCITXDB) 100(GPIO55/SCIRXDB) 101(GPIO56/SCITXDC) 102(GPIO57/SCIRXDC) 103(GPIO58) 104(GPIO59) 105(GPIO60/SPISIMOB) 107(GPIO61/SPISOMIB) 110(GPIO64/SCIRXDA/SPISOMIB) 111(GPIO65/SCITXDA/SPICLKB) 112(GPIO66/SPISTEB) 113(GPIO44/EM1A4) 115(GPIO45/EM1A5) 118(GPIO133) 122(VSSOSC) 128(GPIO46/EM1A6/SCIRXDD) 129(GPIO47/EM1A7/SCITXDD) 130(GPIO42/SCITXDA/USB0DM) 131(GPIO43/USB0DP/SCIRXDA) 133(GPIO68) 134(GPIO69/SPISIMOC/SCLB) 135(GPIO70/CANRXA/SCITXDB) 136(GPIO71/CANTXA/SCIRXDB/SPICLKC) 141(GPIO74) 142(GPIO75) 145(GPIO78) 146(GPIO79) 148(GPIO80) 149(GPIO81) 150(GPIO82) 151(GPIO83) 155(GPIO85/SCIRXDA) 156(GPIO86/SCITXDB/MCLKXA) 157(GPIO87/SCIRXDB) 161(GPIO1/EPWM1B) 163(GPIO3/EPWM2B) 165(GPIO5/EPWM3B) 167(GPIO7/EPWM4B) 170(GPIO88) 171(GPIO89/SCITXDC) 172(GPIO90/SCIRXDC); U36 1(NC); U57 4(NC) 5(MR) 17(NC2) 18(PG2) 20(NC1)

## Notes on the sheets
sheet 1
- 380V--->2.21V
- 430V--->2.501V
- bus voltage sam
- TEMPERATURE MEASUREMENT
- NearDSP
- NearDSP
- bus voltage ovp
- 440V--->2.559V
- NearDSP
- input voltage sample
- dsp
- NearDSP
- PCB Ver.: REV 3
- BOM Ver.: B
- Prepared by:
- Approved by:
- Kevin Xie
- Frank Wei
sheet 2
- NEAR DSP
- output  voltage sample
- NEAR DSP
- CAN
- OVP POINT: 465V
- DC UVP
- NEAR DSP
- UVP POINT: 150V
- PCB Ver.: REV 3
- BOM Ver.: B
- Prepared by:
- Kevin Xie
- Approved by:
- Frank Wei
sheet 3
- Hieght 4.5mm
- PCB Ver.: REV 3
- BOM Ver.: B
- Prepared by:
- Kevin Xie
- Approved by:
- Frank Wei
sheet 4
- NearDSP
- NearDSP
- RMS:0.8V
- PK:1.357V
- NearDSP
- E2PROM
- PCB Ver.: REV 3
- BOM Ver.: B
- Prepared by:
- Kevin Xie
- Approved by:
- Frank Wei
sheet 5
- Near DSP
- Near DSP
- JTAG
- PCB Ver.: REV 3
- BOM Ver.: B
- Prepared by:
- Kevin Xie
- Approved by:
- Frank Wei
- 5V Monitor, <4.2V turn off all PWM
